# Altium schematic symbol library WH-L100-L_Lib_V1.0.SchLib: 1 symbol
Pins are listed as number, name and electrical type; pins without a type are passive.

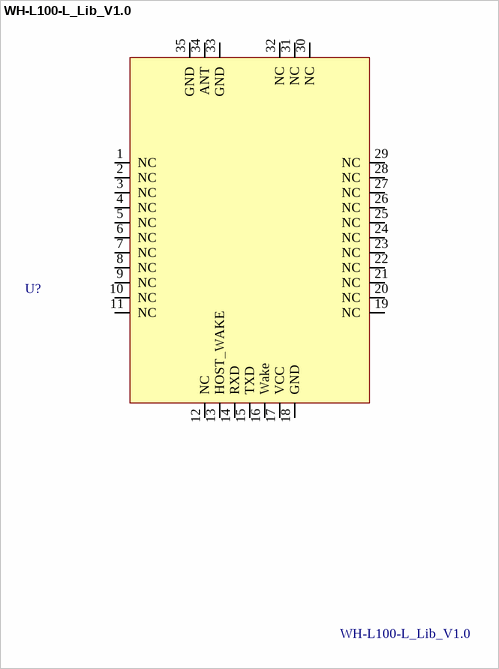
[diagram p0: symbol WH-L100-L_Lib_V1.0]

## WH-L100-L_Lib_V1.0
designator U?
footprint WH-L101-SMT-V1.0 (Footprint not found)
pins: 1 NC, 2 NC, 3 NC, 4 NC, 5 NC, 6 NC, 7 NC, 8 NC, 9 NC, 10 NC, 11 NC, 12 NC, 13 HOST_WAKE, 14 RXD, 15 TXD, 16 Wake, 17 VCC, 18 GND, 19 NC, 20 NC, 21 NC, 22 NC, 23 NC, 24 NC, 25 NC, 26 NC, 27 NC, 28 NC, 29 NC, 30 NC, 31 NC, 32 NC, 33 GND, 34 ANT, 35 GND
